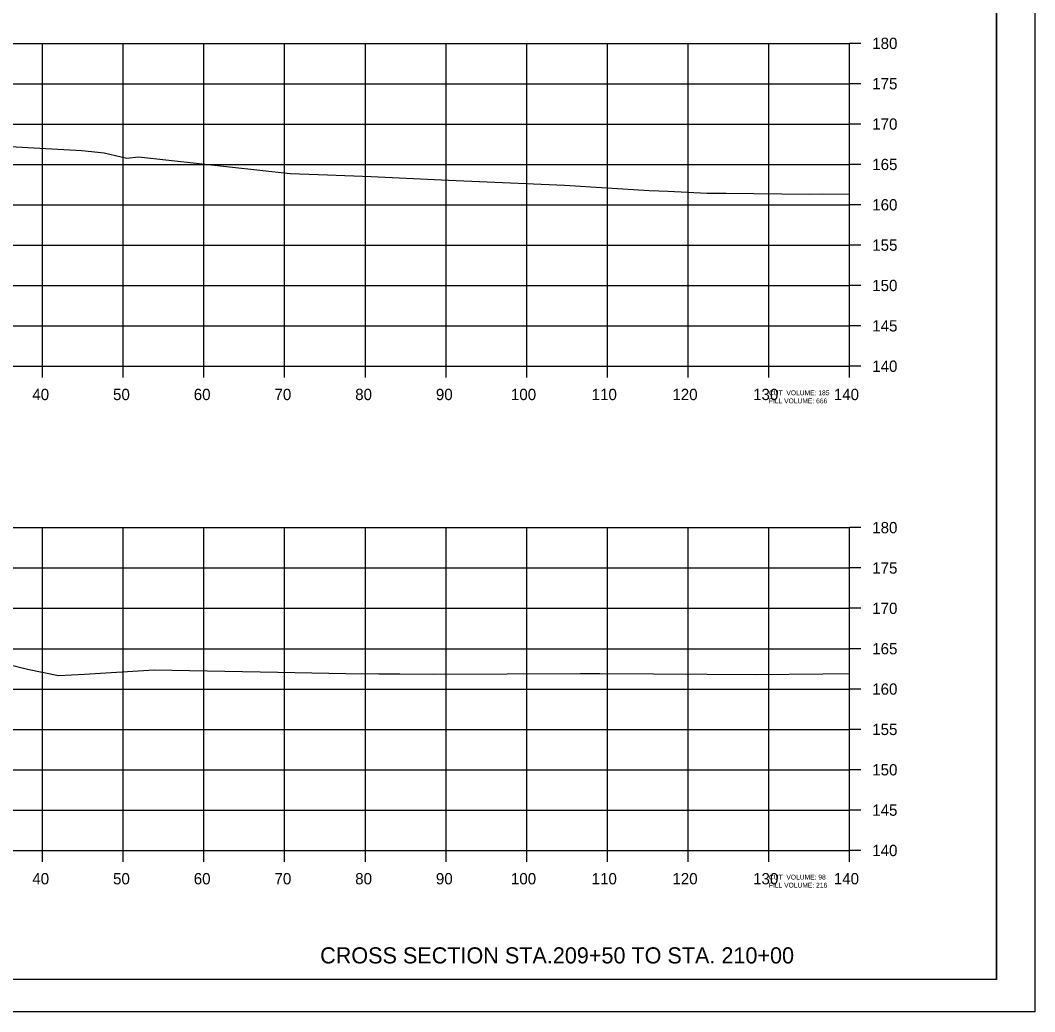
# Model space of a CAD drawing. Extents: x 1368503 to 1373085, y 379840 to 381833.
# Drawn here: x 1368710.3 to 1368836, y 380552.7 to 380675.6 of the extents above; entities that cross this region are included whole.
import ezdxf

# ---------------------------------------------------------------- set-up
doc = ezdxf.new("R2010")
doc.units = 0
for name, color, linetype in [('S_BRIDGE', 7, 'Continuous'), ('S_EDGE_PAVEMENT', 7, 'Continuous'), ('S_MISC_BOUNDARY', 7, 'Continuous'), ('S_PHOTO_CENTERS', 7, 'Continuous'), ('S_PHOTO_NOTES', 7, 'Continuous'), ('S_TRAILS', 7, 'Continuous'), ('S_TREE', 7, 'Continuous')]:
    doc.layers.add(name, color=color, linetype=linetype)

msp = doc.modelspace()

# ---------------------------------------------------------------- linework, layer by layer
at = {"layer": 'S_BRIDGE'}
for q in [(1368831.24, 380762.16), (1368515.06, 380556.7)]:
    msp.add_line((1368831.24, 380556.7), q, dxfattribs=at)
at = {"layer": 'S_EDGE_PAVEMENT'}
for p, q in [((1368813.06, 380632.7), (1368813.06, 380672.7)), ((1368814.46, 380672.7), (1368813.06, 380672.7)), ((1368814.46, 380667.7), (1368813.06, 380667.7)), ((1368814.46, 380662.7), (1368813.06, 380662.7)), ((1368814.46, 380657.7), (1368813.06, 380657.7)), ((1368814.46, 380652.7), (1368813.06, 380652.7)), ((1368814.46, 380647.7), (1368813.06, 380647.7)), ((1368814.46, 380642.7), (1368813.06, 380642.7)), ((1368814.46, 380637.7), (1368813.06, 380637.7)), ((1368533.06, 380632.7), (1368813.06, 380632.7)), ((1368713.06, 380631.3), (1368713.06, 380632.7)), ((1368723.06, 380631.3), (1368723.06, 380632.7)), ((1368733.06, 380631.3), (1368733.06, 380632.7)), ((1368743.06, 380631.3), (1368743.06, 380632.7)), ((1368753.06, 380631.3), (1368753.06, 380632.7)), ((1368763.06, 380631.3), (1368763.06, 380632.7)), ((1368773.06, 380631.3), (1368773.06, 380632.7)), ((1368783.06, 380631.3), (1368783.06, 380632.7)), ((1368793.06, 380631.3), (1368793.06, 380632.7)), ((1368803.06, 380631.3), (1368803.06, 380632.7)), ((1368813.06, 380631.3), (1368813.06, 380632.7)), ((1368814.46, 380632.7), (1368813.06, 380632.7)), ((1368813.06, 380572.7), (1368813.06, 380612.7)), ((1368814.46, 380612.7), (1368813.06, 380612.7)), ((1368814.46, 380607.7), (1368813.06, 380607.7)), ((1368814.46, 380602.7), (1368813.06, 380602.7)), ((1368814.46, 380597.7), (1368813.06, 380597.7)), ((1368814.46, 380592.7), (1368813.06, 380592.7)), ((1368814.46, 380587.7), (1368813.06, 380587.7)), ((1368814.46, 380582.7), (1368813.06, 380582.7)), ((1368814.46, 380577.7), (1368813.06, 380577.7)), ((1368533.06, 380572.7), (1368813.06, 380572.7)), ((1368713.06, 380571.3), (1368713.06, 380572.7)), ((1368723.06, 380571.3), (1368723.06, 380572.7)), ((1368733.06, 380571.3), (1368733.06, 380572.7)), ((1368743.06, 380571.3), (1368743.06, 380572.7)), ((1368753.06, 380571.3), (1368753.06, 380572.7)), ((1368763.06, 380571.3), (1368763.06, 380572.7)), ((1368773.06, 380571.3), (1368773.06, 380572.7)), ((1368783.06, 380571.3), (1368783.06, 380572.7)), ((1368793.06, 380571.3), (1368793.06, 380572.7)), ((1368803.06, 380571.3), (1368803.06, 380572.7)), ((1368813.06, 380571.3), (1368813.06, 380572.7)), ((1368814.46, 380572.7), (1368813.06, 380572.7))]:
    msp.add_line(p, q, dxfattribs=at)
at = {"layer": 'S_MISC_BOUNDARY'}
for points in [[(1368703.79, 380660.19), (1368717.95, 380659.43), (1368720.72, 380659.12), (1368723.51, 380658.48), (1368724.94, 380658.66), (1368743.73, 380656.59), (1368748.39, 380656.42), (1368753.78, 380656.19), (1368763.37, 380655.74), (1368777.72, 380655.13), (1368788.23, 380654.48), (1368789.43, 380654.43), (1368790.57, 380654.38), (1368795.36, 380654.14), (1368797.76, 380654.13), (1368808.08, 380654), (1368809.72, 380654.04), (1368813.06, 380654.01)], [(1368708.38, 380595.85), (1368711.19, 380595.17), (1368715.03, 380594.39), (1368718.28, 380594.53), (1368726.91, 380595.06), (1368742.21, 380594.78), (1368750.63, 380594.63), (1368754.73, 380594.58), (1368757.34, 380594.57), (1368761.56, 380594.55), (1368779.72, 380594.61), (1368781.01, 380594.61), (1368781.43, 380594.61), (1368782.12, 380594.61), (1368795.4, 380594.54), (1368801.36, 380594.52), (1368809.76, 380594.57), (1368813.06, 380594.64)]]:
    msp.add_lwpolyline(points, dxfattribs=at)
at = {"layer": 'S_PHOTO_CENTERS'}
for p, q in [((1368533.06, 380672.7), (1368813.06, 380672.7)), ((1368713.06, 380632.7), (1368713.06, 380672.7)), ((1368723.06, 380632.7), (1368723.06, 380672.7)), ((1368733.06, 380632.7), (1368733.06, 380672.7)), ((1368743.06, 380632.7), (1368743.06, 380672.7)), ((1368753.06, 380632.7), (1368753.06, 380672.7)), ((1368763.06, 380632.7), (1368763.06, 380672.7)), ((1368773.06, 380632.7), (1368773.06, 380672.7)), ((1368783.06, 380632.7), (1368783.06, 380672.7)), ((1368793.06, 380632.7), (1368793.06, 380672.7)), ((1368803.06, 380632.7), (1368803.06, 380672.7)), ((1368813.06, 380632.7), (1368813.06, 380672.7)), ((1368533.06, 380667.7), (1368813.06, 380667.7)), ((1368533.06, 380662.7), (1368813.06, 380662.7)), ((1368533.06, 380657.7), (1368813.06, 380657.7)), ((1368533.06, 380652.7), (1368813.06, 380652.7)), ((1368533.06, 380647.7), (1368813.06, 380647.7)), ((1368533.06, 380642.7), (1368813.06, 380642.7)), ((1368533.06, 380637.7), (1368813.06, 380637.7)), ((1368533.06, 380632.7), (1368813.06, 380632.7)), ((1368533.06, 380612.7), (1368813.06, 380612.7)), ((1368713.06, 380572.7), (1368713.06, 380612.7)), ((1368723.06, 380572.7), (1368723.06, 380612.7)), ((1368733.06, 380572.7), (1368733.06, 380612.7)), ((1368743.06, 380572.7), (1368743.06, 380612.7)), ((1368753.06, 380572.7), (1368753.06, 380612.7)), ((1368763.06, 380572.7), (1368763.06, 380612.7)), ((1368773.06, 380572.7), (1368773.06, 380612.7)), ((1368783.06, 380572.7), (1368783.06, 380612.7)), ((1368793.06, 380572.7), (1368793.06, 380612.7)), ((1368803.06, 380572.7), (1368803.06, 380612.7)), ((1368813.06, 380572.7), (1368813.06, 380612.7)), ((1368533.06, 380607.7), (1368813.06, 380607.7)), ((1368533.06, 380602.7), (1368813.06, 380602.7)), ((1368533.06, 380597.7), (1368813.06, 380597.7)), ((1368533.06, 380592.7), (1368813.06, 380592.7)), ((1368533.06, 380587.7), (1368813.06, 380587.7)), ((1368533.06, 380582.7), (1368813.06, 380582.7)), ((1368533.06, 380577.7), (1368813.06, 380577.7)), ((1368533.06, 380572.7), (1368813.06, 380572.7))]:
    msp.add_line(p, q, dxfattribs=at)
at = {"layer": 'S_PHOTO_NOTES'}
msp.add_line((1368502.66, 380552.73), (1368835.99, 380552.73), dxfattribs=at)
for points in [[(1368502.65, 380766.06), (1368835.99, 380766.06), (1368835.99, 380552.72), (1368502.65, 380552.72)], [(1368748.98, 380762.16), (1368748.98, 380752.28), (1368784.71, 380752.28), (1368784.71, 380749.36), (1368807.91, 380749.36), (1368807.91, 380725.03), (1368831.24, 380725.03), (1368831.24, 380556.7), (1368515.06, 380556.7), (1368515.06, 380762.16)]]:
    msp.add_lwpolyline(points, close=True, dxfattribs=at)

# ---------------------------------------------------------------- texts
at = {"layer": 'S_TRAILS'}
for s, height, p in [('180', 1.4, (1368815.86, 380672)), ('175', 1.4, (1368815.86, 380667)), ('170', 1.4, (1368815.86, 380662)), ('165', 1.4, (1368815.86, 380657)), ('160', 1.4, (1368815.86, 380652)), ('155', 1.4, (1368815.86, 380647)), ('150', 1.4, (1368815.86, 380642)), ('145', 1.4, (1368815.86, 380637)), ('140', 1.4, (1368815.86, 380632)), ('40', 1.4, (1368711.8, 380628.5)), ('50', 1.4, (1368721.8, 380628.5)), ('60', 1.4, (1368731.8, 380628.5)), ('70', 1.4, (1368741.8, 380628.5)), ('80', 1.4, (1368751.8, 380628.5)), ('90', 1.4, (1368761.8, 380628.5)), ('100', 1.4, (1368771.1, 380628.5)), ('110', 1.4, (1368781.1, 380628.5)), ('120', 1.4, (1368791.1, 380628.5)), ('130', 1.4, (1368801.1, 380628.5)), ('140', 1.4, (1368811.1, 380628.5)), ('CUT  VOLUME: 185', 0.6, (1368803.06, 380629.1)), ('FILL VOLUME: 666', 0.6, (1368803.06, 380628.1)), ('180', 1.4, (1368815.86, 380612)), ('175', 1.4, (1368815.86, 380607)), ('170', 1.4, (1368815.86, 380602)), ('165', 1.4, (1368815.86, 380597)), ('160', 1.4, (1368815.86, 380592)), ('155', 1.4, (1368815.86, 380587)), ('150', 1.4, (1368815.86, 380582)), ('145', 1.4, (1368815.86, 380577)), ('140', 1.4, (1368815.86, 380572)), ('40', 1.4, (1368711.8, 380568.5)), ('50', 1.4, (1368721.8, 380568.5)), ('60', 1.4, (1368731.8, 380568.5)), ('70', 1.4, (1368741.8, 380568.5)), ('80', 1.4, (1368751.8, 380568.5)), ('90', 1.4, (1368761.8, 380568.5)), ('100', 1.4, (1368771.1, 380568.5)), ('110', 1.4, (1368781.1, 380568.5)), ('120', 1.4, (1368791.1, 380568.5)), ('130', 1.4, (1368801.1, 380568.5)), ('CUT  VOLUME: 98', 0.6, (1368803.06, 380569.1)), ('140', 1.4, (1368811.1, 380568.5)), ('FILL VOLUME: 216', 0.6, (1368803.06, 380568.1))]:
    msp.add_text(s, height=height, dxfattribs=at).set_placement(p)
at = {"layer": 'S_TREE'}
msp.add_text('CROSS SECTION STA.209+50 TO STA. 210+00', height=2, dxfattribs=at).set_placement((1368747.46, 380558.7))

doc.saveas('drawing.dxf')
